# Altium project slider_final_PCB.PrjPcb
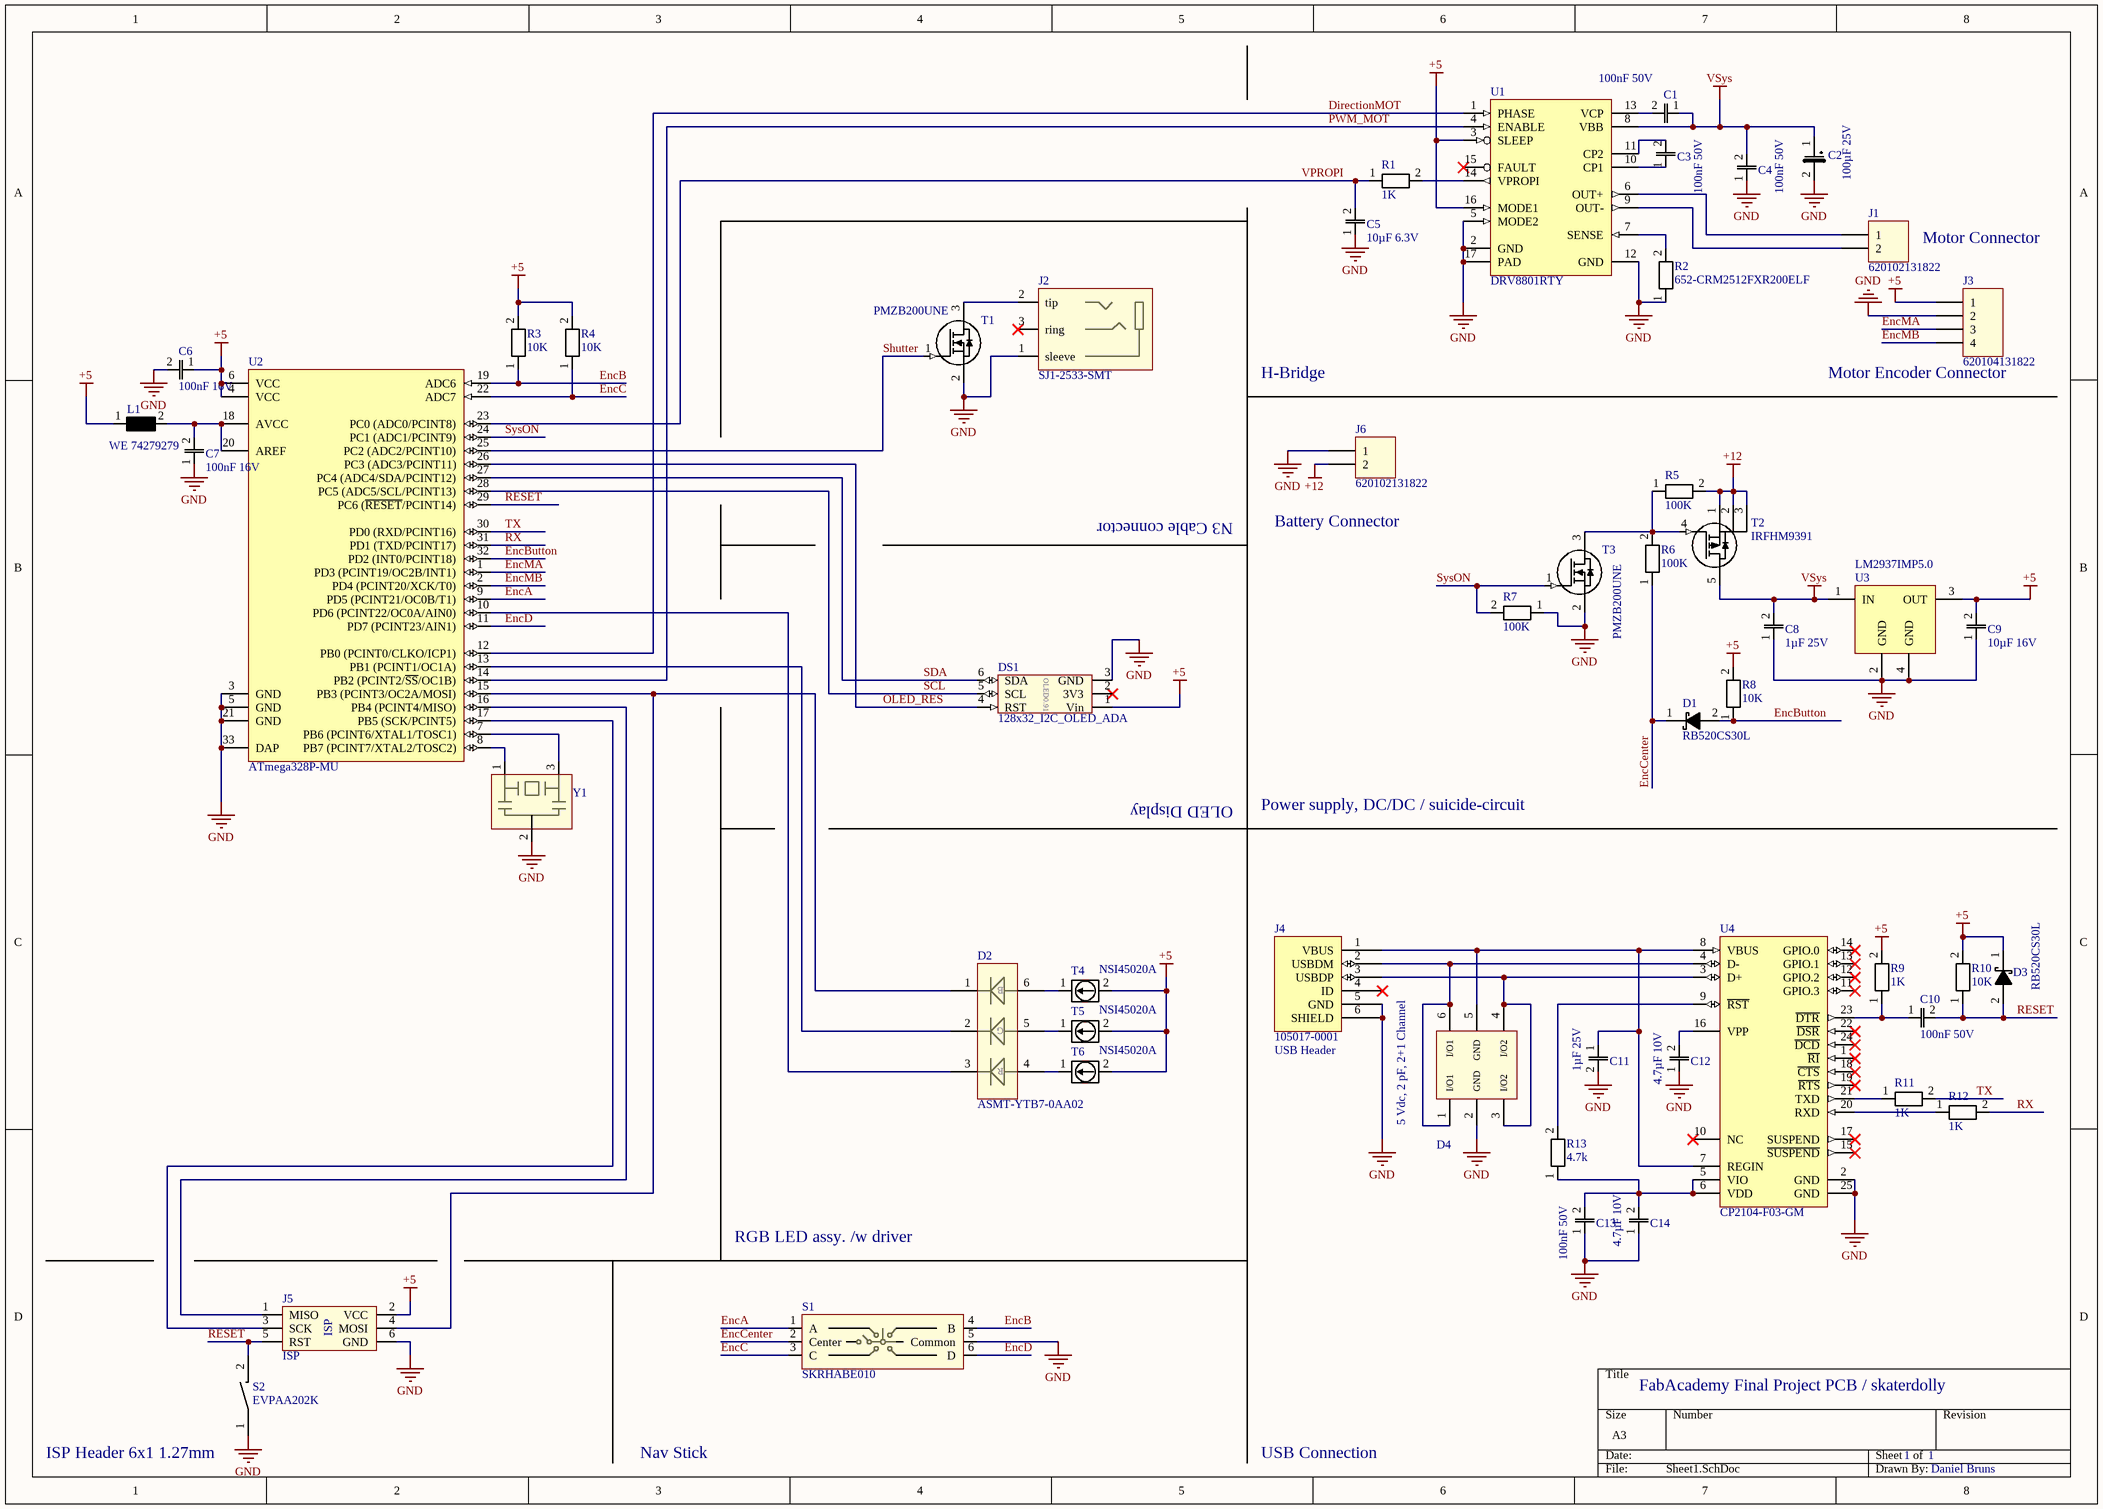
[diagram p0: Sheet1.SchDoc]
1 sheet, 52 parts. Net scope: global (net labels, ports and power ports of the same name join across sheets).

## Sheet Sheet1.SchDoc: FabAcademy Final Project PCB / skaterdolly
size A3; CompanyName: Blackballs Technologies GmbH; DrawnBy: Daniel Bruns; SheetNumber: 1; SheetTotal: 1; PageSetup: Record=PageOptions¦CenterHorizontal=True¦CenterVertical=True¦PrintScale=2.47¦XCorrection=1.00¦YCorrection=1.00¦PrintKind=0¦BorderSize=5000000¦LeftOffset=0¦BottomOffset=0¦Orientation=2¦PaperLength=1000¦PaperWidth=1000¦Scale=100¦PaperSource=7¦PrintQuality=-3¦MediaType=1¦DitherType=10¦PrintScaleMode=1¦PaperKind=A3¦PaperIndex=8

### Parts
C1  value 100nF 50V  [C 0402]  (hidden comment: GRM155R61H104KE19D)
C2  value 100µF 25V  [C 7343]  (hidden comment: T491X107K025AT)
C3  value 100nF 50V  [C 0402]  (hidden comment: GRM155R61H104KE19D)
C4  value 100nF 50V  [C 0402]  (hidden comment: GRM155R61H104KE19D)
C5  value 10µF 6.3V  [C 0402]  (hidden comment: GRM155R60J106ME44D)
C6  value 100nF 16V  [C 0402]  (hidden comment: GRM155R71C104KA88D)
C7  value 100nF 16V  [C 0402]  (hidden comment: GRM155R71C104KA88D)
C8  value 1µF 25V  [C 0402]  (hidden comment: GRM155R61E105KA12D)
C9  value 10µF 16V  [C 0603]  (hidden comment: GRM188R61C106MA73D)
C10  value 100nF 50V  [C 0402]  (hidden comment: GRM155R61H104KE19D)
C11  value 1µF 25V  [C 0402]  (hidden comment: GRM155R61E105KA12D)
C12  value 4.7µF 10V  [C 0603]  (hidden comment: GRM188R61A475KE5D)
C13  value 100nF 50V  [C 0402]  (hidden comment: GRM155R61H104KE19D)
C14  value 4.7µF 10V  [C 0603]  (hidden comment: GRM188R61A475KE5D)
D1  RB520CS30L  [NXP SOD882]
D2  ASMT-YTB7-0AA02  [ASMT-YTB7-0AA02]
D3  RB520CS30L  [NXP SOD882]
D4  5 Vdc, 2 pF, 2+1 Channel  [SOT563_High Speed Series]
DS1  128x32_I2C_OLED_ADA  [128x32_I2C_OLED_ADA - SMT]
J1  620102131822  [620102131822]
J2  SJ1-2533-SMT  [SJ1-2533-SMT]
J3  620104131822  [620104131822]
J4  105017-0001  [Molex 105017-0001]
J5  ISP  [PIN HEADER 1X6 TH Pitch 1.27]
J6  620102131822  [620102131822]
L1  WE 74279279  [WE CBF 0402]
R1  value 1K  [R 0402]  (hidden comment: CRCW04021K00FKED)
R2  Supplier Part Number 1: 652-CRM2512FXR200ELF  [BOURNS CRM2512]  (hidden comment: CRM2512-FX-R200ELF)
R3  value 10K  [R 0402]  (hidden comment: CRCW040210K0FKED)
R4  value 10K  [R 0402]  (hidden comment: CRCW040210K0FKED)
R5  value 100K  [R 0402]  (hidden comment: R 0402 100K)
R6  value 100K  [R 0402]  (hidden comment: R 0402 100K)
R7  value 100K  [R 0402]  (hidden comment: R 0402 100K)
R8  value 10K  [R 0402]  (hidden comment: CRCW040210K0FKED)
R9  value 1K  [R 0402]  (hidden comment: CRCW04021K00FKED)
R10  value 10K  [R 0402]  (hidden comment: CRCW040210K0FKED)
R11  value 1K  [R 0402]  (hidden comment: CRCW04021K00FKED)
R12  value 1K  [R 0402]  (hidden comment: CRCW04021K00FKED)
R13  value 4.7k  [R 0402]  (hidden comment: CRCW04024K70FKEDHP)
S1  SKRHABE010  [SKRHABE010]
S2  EVPAA202K  [Panasonic EVPAA]
T1  PMZB200UNE  [DFN1006B-3 (SOT883B)]
T2  IRFHM9391  [IRF PQFN 3.3x3.3 B]
T3  PMZB200UNE  [DFN1006B-3 (SOT883B)]
T4  NSI45020A  [ONSEMI SOD123]
T5  NSI45020A  [ONSEMI SOD123]
T6  NSI45020A  [ONSEMI SOD123]
U1  DRV8801RTY  [TI RTY S-PQFN-N16]
U2  ATmega328P-MU  [32M1-A_M]
U3  LM2937IMP5.0  [SOT223-4]
U4  CP2104-F03-GM  [SLAB-QFN-24-2675x2675TP_M]
Y1  PRQV16.00CR1510Y00L  [PRQC8.00CR1010V00L]  (value not drawn)

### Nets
+5: C6.1 C9.2 D3.1(K) DS1.1(Vin) J3.1 J5.2(VCC) L1.1 R3.2 R4.2 R8.2 R9.2 R10.2 T4.2(A) T5.2(A) T6.2(A) U1.3(SLEEP) U1.16(MODE1) U2.4(VCC) U2.6(VCC) U3.3(OUT)
+12: J6.2 R5.2 T2.1(S) T2.2(S) T2.3(S)
GND: C2.2 C4.1 C5.1 C6.2 C7.1 C8.1 C9.1 C11.2 C12.1 C13.1 C14.1 D4.2(GND) DS1.3(GND) J2.1(sleeve) J3.2 J4.5(GND) J4.6(SHIELD) J5.6(GND) J6.1 R2.1 R7.1 S1.5(Common) S2.1 T1.2(D) T3.2(D) U1.2(GND) U1.5(MODE2) U1.12(GND) U1.17(PAD) U2.3(GND) U2.5(GND) U2.21(GND) U2.33(DAP) U3.2(GND) U3.4(GND) U4.2(GND) U4.25(GND) Y1.2(GND)
VSys: C1.1 C2.1 C4.2 C8.2 T2.5(D) U1.8(VBB) U3.1(IN)
DirectionMOT: U1.1(PHASE) U2.12(PB0_(PCINT0/CLKO/ICP1))
EncA: S1.1(A) U2.9(PD5_(PCINT21/OC0B/T1))
EncB: R3.1 S1.4(B) U2.19(ADC6)
EncButton: D1.2(A) R8.1 U2.32(PD2_(INT0/PCINT18))
EncC: R4.1 S1.3(C) U2.22(ADC7)
EncCenter: D1.1(K) R6.1 S1.2(Center)
EncD: S1.6(D) U2.11(PD7_(PCINT23/AIN1))
EncMA: J3.3 U2.1(PD3_(PCINT19/OC2B/INT1))
EncMB: J3.4 U2.2(PD4_(PCINT20/XCK/T0))
OLED_RES: DS1.4(RST) U2.26(PC3_(ADC3/PCINT11))
PWM_MOT: U1.4(ENABLE) U2.14(PB2_(PCINT2/~{SS}/OC1B))
RESET: C10.2 D3.2(A) J5.5(RST) R10.1 S2.2 U2.29(PC6_(~{RESET}/PCINT14))
RX: R12.2 U2.31(PD1_(TXD/PCINT17))
SCL: DS1.5(SCL) U2.28(PC5_(ADC5/SCL/PCINT13))
SDA: DS1.6(SDA) U2.27(PC4_(ADC4/SDA/PCINT12))
Shutter: T1.1(G) U2.25(PC2_(ADC2/PCINT10))
SysON: R7.2 T3.1(G) U2.24(PC1_(ADC1/PCINT9))
TX: R11.2 U2.30(PD0_(RXD/PCINT16))
VPROPI: C5.2 R1.1 U2.23(PC0_(ADC0/PCINT8))
NetC1_2: C1.2 U1.13(VCP)
NetC3_1: C3.1 U1.10(CP1)
NetC3_2: C3.2 U1.11(CP2)
NetC7_2: C7.2 L1.2 U2.18(AVCC) U2.20(AREF)
NetC10_1: C10.1 R9.1 U4.23(~{DTR})
NetC11_1: C11.1 D4.5(GND) J4.1(VBUS) U4.7(REGIN) U4.8(VBUS)
NetC12_2: C12.2 U4.16(VPP)
NetC13_2: C13.2 C14.2 R13.1 U4.5(VIO) U4.6(VDD)
NetD2_1: D2.1 J5.4(MOSI) U2.15(PB3_(PCINT3/OC2A/MOSI))
NetD2_2: D2.2 U2.13(PB1_(PCINT1/OC1A))
NetD2_3: D2.3 U2.10(PD6_(PCINT22/OC0A/AIN0))
NetD2_4: D2.4 T6.1(K)
NetD2_5: D2.5 T5.1(K)
NetD2_6: D2.6 T4.1(K)
NetD4_1: D4.1(I/O1) D4.6(I/O1) J4.2(USBDM) U4.4(D-)
NetD4_3: D4.3(I/O2) D4.4(I/O2) J4.3(USBDP) U4.3(D+)
NetJ1_1: J1.1 U1.6(OUT+)
NetJ1_2: J1.2 U1.9(OUT-)
NetJ2_2: J2.2(tip) T1.3(S)
NetJ5_1: J5.1(MISO) U2.16(PB4_(PCINT4/MISO))
NetJ5_3: J5.3(SCK) U2.17(PB5_(SCK/PCINT5))
NetR1_2: R1.2 U1.14(VPROPI)
NetR2_2: R2.2 U1.7(SENSE)
NetR5_1: R5.1 R6.2 T2.4(G) T3.3(S)
NetR11_1: R11.1 U4.21(TXD)
NetR12_1: R12.1 U4.20(RXD)
NetR13_2: R13.2 U4.9(~{RST})
NetU2_7: U2.7(PB6_(PCINT6/XTAL1/TOSC1)) Y1.3
NetU2_8: U2.8(PB7_(PCINT7/XTAL2/TOSC2)) Y1.1

Not connected (* = marked no-connect by the designer): DS1 2(3V3)*; J2 3(ring)*; J4 4(ID)*; U1 15(FAULT)*; U4 1(~{RI})* 10(NC)* 11(GPIO.3)* 12(GPIO.2)* 13(GPIO.1)* 14(GPIO.0)* 15(~{SUSPEND})* 17(SUSPEND)* 18(~{CTS})* 19(~{RTS})* 22(~{DSR})* 24(~{DCD})*

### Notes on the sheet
- Motor Connector
- H-Bridge
- (near J3) Motor Encoder Connector
- N3 Cable connector
- (near J6) Battery Connector
- OLED Display
- Power supply, DC/DC / suicide-circuit
- (near J4) USB Header
- RGB LED assy. /w driver
- (near S2) ISP Header 6x1 1.27mm
- Nav Stick
- USB Connection

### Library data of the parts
C1 C3 C4 C10 C13 = C 0402 100nF 50V X5R
C2 = C 7343 100uF 25V Tantal
C5 = C 0402 10uF 6.3V X5R
C6 C7 = C 0402 100nF 16V X7R
C8 C11 = C 0402 1uF 25V X5R
C9 = C 0603 10uF 16V X5R
C12 C14 = C 0603 4.7uF 10V X5R
D1 D3 = RB520CS30L: 30V / 0.1A Schottky Diode
D2 = ASMT-YTB7-0AA02: LED RGB 50,25,25mA 2.1V 3.1V 3.1V
D4 = 82400152: WE-TVS TVS Diode, High Speed Series, SOT563, 5 Vdc, 2 pF, 2+1 Channel; Reverse Breakdown Voltage: 6 V; Reverse Stand-Off Voltage: 5 V; Channel Input Capacitance: 2 pF
DS1 = 128x32_I2C_OLED_ADA: OLED 0.91" 128x32 I2C 3V3 5V
J1 J6 = 620102131822: WR-WTB 2.00mm SMT Male Horizontal Shrouded Header, 2p; Pin Number: 2
J2 = SJ1-2533-SMT: 2.5mm 3P TRS conn. no switch
J3 = 620104131822: WR-WTB 2.00mm SMT Male Horizontal Shrouded Header, 4p; Pin Number: 4
J4 = 105017-0001: Molex USB Micro-B Jack
J5 = ISP: Atmel ISP 6P Header
L1 = WE 74279279: EMI suppression bead, 600Ohm @ 100MHz, max @ 180MHz, 0402
R1 R9 R11 R12 = R 0402 1K 63mW
R2 = R 2512 0R2 2W
R3 R4 R8 R10 = R 0402 10K 63mW
R13 = R 0402 4.7K 125mW
S1 = SKRHABE010: 4 direction center push SMD Switch
S2 = EVPAA202K: Miniature Switch SPST-NO SMT
T1 T3 = PMZB200UNE: 30V/1.4A N-Channel MOSFET
T2 = IRFHM9391: P-Channel MOSFET -30V -11A
T4-T6 = NSI45020AT1G: 20mA constant current LED driver
U1 = DRV8801RTY: Integrated H-Bridge 36V 2.8A QFN-16
U2 = ATmega328P-MU: 8-bit AVR Microcontroller, 32KB Flash, 1KB EEPROM, 2KB SRAM, 32-pin MLF, Industrial Grade (-40°C to 85°C)
U3 = LM2937IMP5.0: Linear regulator 5.0V / 500mA
U4 = CP2104-F03-GM: Single-Chip USB to UART Bridge, 4 Dig I/O Pins, Internal Oscillator, 1024 Bytes EEPROM, -40 to 85 degC, 24-pin QFN; Manufacturer: Silicon Labs; Internal Oscillator: TRUE; Sub-Family: USB Bridges
Y1 = PRQV16.00CR1510Y00L: AVX 16MHz ceramic resonator SMD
